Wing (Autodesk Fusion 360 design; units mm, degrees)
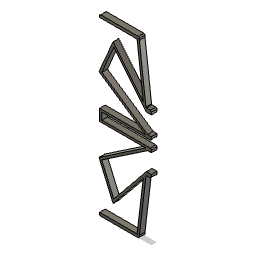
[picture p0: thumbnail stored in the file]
parameter "half_length" = 30 (= "1.5 * diameter / 2")
parameter "thickness" = 0.8
parameter "a1" = 12.5
parameter "a2" = 22
parameter "a3" = 34
parameter "a5" = 56
parameter "a6" = 57
parameter "a7" = 85
parameter "f1" = "1.05"
parameter "t2" = 3
parameter "width" = 2
parameter "diameter" = 40
parameter "d147" = 1
parameter "d160" = 1
parameter "d166" = 1.25
sketch "Sketch1" plane through (0, 0, 0) normal (0, 0, 1) x axis (1, 0, 0)
  line L1 (-20.8, 30) -> (0, 30)
  line L2 (0, 30) -> (0, 0)
  line L3 (0, 0) -> (-20, 0)
  line L4 (-20, 13.4902) -> (0, 0)
  line L5 (-6.6508, 30) -> (0, 0)
  line L6 (-20.8, 31) -> (-20.8, 30)
  line L7 (0, 31) -> (-20.8, 31)
  line L8 (0, 30) -> (0, 31)
  line L9 (-3.2591, 8.0665) -> (0, 0)
  line L10 (-15.7692, 23.3789) -> (0, 0)
  line L11 (-1.887, 1.2254) -> (0, 0)
  line L12 (-20, 1.2254) -> (-20, 0)
  line L13 (-1.887, 1.2254) -> (-20, 1.2254)
  line L14 (-20, 13.4902) -> (-1.887, 1.2254)
  line L15 (-15.7692, 23.3789) -> (-20, 13.4902)
  line L16 (-3.2591, 8.0665) -> (-15.7692, 23.3789)
  line L17 (-6.6508, 30) -> (-1.883, 8.4938)
  line L18 (-20, 0) -> (-20.8, 0)
  line L19 (-20.8, 2.0254) -> (-20.8, 0)
  line L20 (-4.4953, 2.0254) -> (-20.8, 2.0254)
  line L21 (-20.9952, 13.1979) -> (-4.4953, 2.0254)
  line L22 (-15.9853, 24.9077) -> (-20.9952, 13.1979)
  line L23 (-2.4548, 8.3465) -> (-15.9853, 24.9077)
  line L24 (-6.6508, 31) -> (-6.6508, 30)
  line L25 (-3.9809, 7.7358) -> (-6.6508, 30)
  line L26 (-5.2736, 11.7967) -> (-7.4566, 30)
  circle C1 centre (0, 0) radius 2.25
  circle C2 centre (0, 0) radius 3.61
  circle C3 centre (0, 0) radius 8.7
  circle C4 centre (0, 0) radius 10.06
  arc A1 centre (0, 0) radius 8.7 clockwise from (-3.2591, 8.0665) to (-3.9809, 7.7358)
  point P1 (0, 0)
  point P2 (0, 30)
  point P4 (0, 0)
  point P6 (0, 0)
  point P7 (0, 0)
  point P9 (0, 0)
  point P10 (-6.6508, 30)
  point P13 (-1.883, 8.4938)
  point P14 (-6.6508, 30)
  point P15 (0, 0)
  point P17 (-3.2591, 8.0665)
  point P18 (0, 0)
  point P16 (-3.2591, 8.0665)
  point P20 (0, 0)
  point P22 (-3.2591, 8.0665)
  point P23 (-1.883, 8.4938)
  point P24 (-6.6508, 30)
  point P25 (-20, 0)
  point P26 (-20, 0)
  point P3 (-20.8, 30)
  point P28 (-20.8, 2.0254)
  point P5 (-20, 1.2254)
  point P8 (-20, 13.4902)
  point P32 (0, 0)
  point P21 (-1.887, 1.2254)
  point P34 (0, 0)
  point P36 (-2.4548, 8.3465)
  point P37 (-6.6508, 30)
  point P38 (-6.6508, 31)
  point P39 (-6.6508, 30)
  point P41 (-7.4566, 30)
  point P42 (-5.2736, 11.7967)
  point P44 (-3.9809, 7.7358)
  point P45 (-3.2591, 8.0665)
  point P43 (0, 0)
  point P40 (-3.9809, 7.7358)
  point P11 (-20.8, 31)
  point P19 (-15.7692, 23.3789)
  horizontal L1
  vertical P1 P2
  coincident P1 P4
  coincident P1 P6
  perpendicular L2 L3
  coincident P1 P7
  coincident P1 P9
  perpendicular L1 L6
  horizontal L7
  perpendicular L1 L8
  coincident L1 P10
  coincident L5 P13
  coincident P10 P14
  coincident P1 P15
  coincident L9 P17
  coincident P1 P18
  coincident P16 P17
  coincident P1 P20
  coincident P17 P22
  coincident P13 P23
  coincident P14 P24
  vertical L12
  coincident P25 P26
  horizontal L13
  vertical P3 P28
  perpendicular L12 L18
  vertical P5 P8
  coincident P1 P32
  coincident P21 C1
  coincident P4 P34
  coincident P13 C3
  coincident C3 P36
  coincident L1 P37
  coincident L7 P38
  perpendicular L7 L24
  coincident P14 L24
  coincident P14 P39
  coincident L1 P41
  coincident L23 P42
  parallel L25 L26
  coincident L25 P44
  coincident P17 P45
  coincident P32 P43
  coincident C3 P40
  dimension "d40" distance P1 P2 = 30 (= "half_length")
  dimension "d45" angle L2 L4 = 56 (= "a5")
  dimension "d47" angle L2 L5 = 12.5 (= "a1")
  dimension "d57" distance P3 P11 = 1
  dimension "d66" distance P1 P13 = 8.7 (= "f2 * half_length")
  dimension "d67" angle L2 L9 = 22 (= "a2")
  dimension "d68" distance P1 P17 = 8.7 (= "f2 * half_length")
  dimension "d69" angle L2 L10 = 34 (= "a3")
  dimension "d70" distance P1 P19 = 28.2 (= "f3 * half_length")
  dimension "d72" angle L2 L11 = 57 (= "a6")
  dimension "d73" distance P1 P21 = 2.25 (= "f7 * half_length / 2")
  dimension "d86" distance P6 P25 = 20 (= "diameter / 2")
  dimension "d88" = 1.36 (= "thickness * 1.7")
  dimension "d89" = 1.36 (= "d88")
  dimension "d142" distance L16 L23 = 0.8 (= "thickness")
  dimension "d143" distance L14 L21 = 0.8 (= "thickness")
  dimension "d144" distance L15 L22 = 0.8 (= "thickness")
  dimension "d145" distance L13 L20 = 0.8 (= "thickness")
  dimension "d146" distance L12 L19 = 0.8 (= "thickness")
  dimension "d157" distance L2 P40 = 3.9809 (= "( 2.5 * 10 / ( 2 * 3.14 ) ) * 1 mm")
  dimension "d159" distance L25 L26 = 0.8 (= "thickness")
extrude "Extrude1" new body sketch "Sketch1" profile of L1 L6 L7 L12 L13 L14 L15 L16 L22 L23 L21 L20 L19 L18 C2 C4 L24 L25 L26 distance 1 (= "width / 2")
fillet "Fillet3" radius 0.25
fillet "Fillet4" radius 1
fillet "Fillet5" radius 0.25
sketch "Sketch7" plane through (0, 0, 1) normal (0, 0, 1) x axis (1, 0, 0)
  line L1 (-15.9853, 24.9077) -> (-5.2736, 11.7967)
  line L2 (-20.9952, 13.1979) -> (-15.9853, 24.9077)
  line L3 (-4.4953, 2.0254) -> (-20.9952, 13.1979)
  line L4 (-20, 13.4902) -> (-3.0133, 1.9881)
  line L5 (-15.7692, 23.3789) -> (-20, 13.4902)
  line L6 (-4.1543, 9.1622) -> (-15.7692, 23.3789)
  line L7 (-7.4566, 30) -> (-20.8, 30)
  line L8 (-5.2736, 11.7967) -> (-7.4566, 30)
  line L9 (-6.6508, 30) -> (-4.3293, 10.6409)
  line L10 (-6.6508, 31) -> (-6.6508, 30)
  line L11 (-20.8, 31) -> (-6.6508, 31)
  line L12 (-20.8, 30) -> (-20.8, 31)
  line L13 (-20.8, 2.0254) -> (-4.4953, 2.0254)
  line L14 (-20.8, 0) -> (-20.8, 2.0254)
  line L15 (-20, 0) -> (-20.8, 0)
  line L16 (-20, 1.2254) -> (-20, 0)
  line L17 (-3.3956, 1.2254) -> (-20, 1.2254)
  line L18 (-2.3956, 1.2254) -> (-3.3956, 1.2254)
  line L19 (-2.3956, 2.4754) -> (-2.3956, 1.2254)
  line L20 (-3.7331, 2.4754) -> (-2.3956, 2.4754)
  line L21 (-2.3956, 9.1622) -> (-4.1543, 9.1622)
  line L22 (-2.3956, 10.4122) -> (-2.3956, 9.1622)
  line L23 (-5.1755, 10.4122) -> (-2.3956, 10.4122)
  line L24 (-4.3293, 10.6409) -> (-3.3776, 9.476)
  arc A1 centre (0, 0) radius 3.61 clockwise from (-3.3956, 1.2254) to (-3.0133, 1.9881)
  arc A2 centre (0, 0) radius 10.06 clockwise from (-4.1543, 9.1622) to (-3.3776, 9.476)
  point P22 (-3.3956, 1.2254)
  point P24 (-3.3956, 1.2254)
  point P27 (-3.7331, 2.4754)
  point P17 (-4.1543, 9.1622)
  point P28 (-4.1543, 9.1622)
  point P31 (-5.1755, 10.4122)
  point P26 (-2.3956, 2.4754)
  point P29 (-2.3956, 9.1622)
  point P25 (-2.3956, 1.2254)
  point P30 (-2.3956, 10.4122)
  coincident P22 P24
  horizontal L18
  perpendicular L18 L19
  coincident L4 P27
  perpendicular L19 L20
  coincident P17 P28
  horizontal L21
  perpendicular L21 L22
  coincident L6 P31
  perpendicular L22 L23
  vertical P26 P29
  dimension "d169" distance P25 P26 = 1.25
  dimension "d170" distance P24 P25 = 1
  dimension "d171" distance P29 P30 = 1.25 (= "d169")
extrude "Extrude9" add sketch "Sketch7" profile of L1 L2 L3 L4 L5 L6 L7 L8 L9 L10 L11 L12 L13 L14 L15 L16 L17 A1 L18 L19 L20 L21 L22 L23 to an object
fillet "Fillet11" radius 0.4
mirror "Mirror3" mirrorStitchTolerance 0.1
